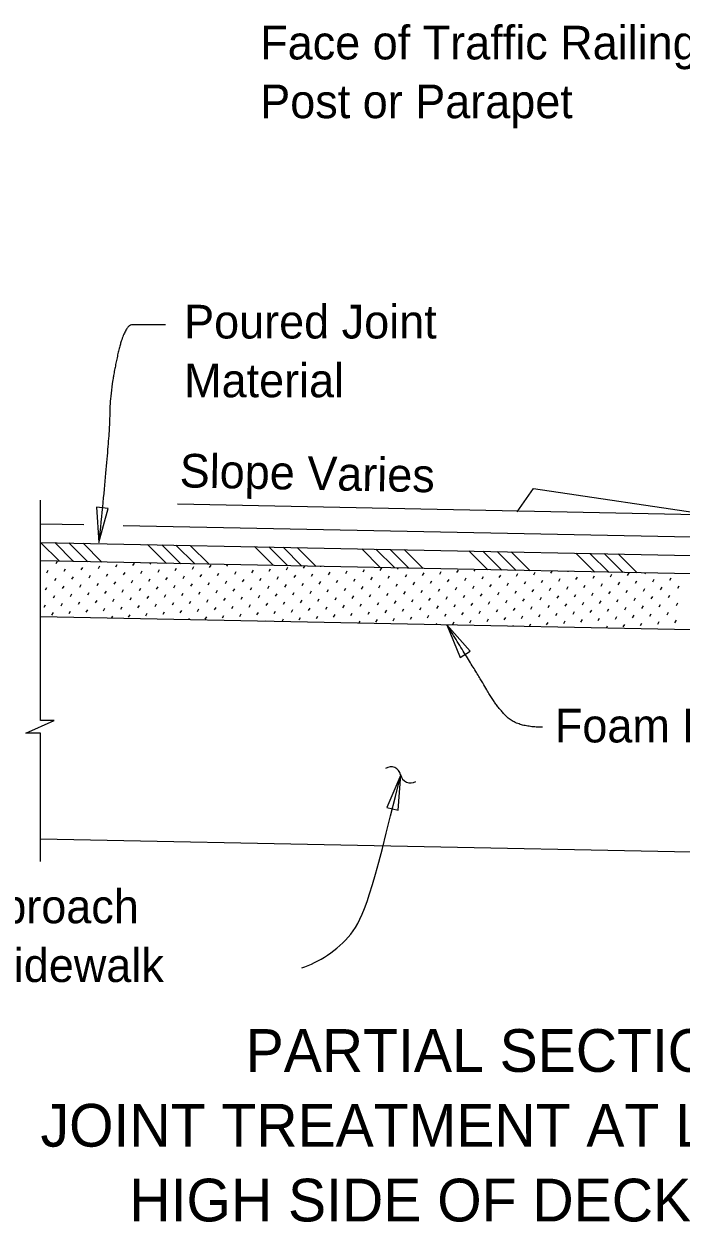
# Model space of a CAD drawing. Extents: x -7.9 to 27, y -3.1 to 14.6.
# Drawn here: x 9.806 to 11.283, y 11.645 to 14.336 of the extents above; entities that cross this region are included whole.
import ezdxf

# ---------------------------------------------------------------- set-up
doc = ezdxf.new("R2010")
doc.units = 0
for name, color, linetype in [('Border', 7, 'Continuous'), ('Patterning', 7, 'Continuous'), ('PlotBorder_dp', 7, 'Continuous'), ('TextMisc', 7, 'Continuous')]:
    doc.layers.add(name, color=color, linetype=linetype)

msp = doc.modelspace()

# ---------------------------------------------------------------- linework, layer by layer
at = {"layer": 'Patterning'}
for p, q in [((9.8432, 13.2133), (9.9407, 13.2114)), ((10.0289, 13.2096), (11.9108, 13.172)), ((13.1635, 12.4386), (9.8432, 12.5051))]:
    msp.add_line(p, q, dxfattribs=at)
at = {"layer": 'PlotBorder_dp'}
for points in [[(10.9147, 13.2405), (10.9512, 13.2929), (11.3547, 13.2329), (10.1512, 13.257)], [(9.8431, 12.4546), (9.8431, 12.7428), (9.8101, 12.7428), (9.8741, 12.7711), (9.8431, 12.7711), (9.8431, 13.2661)]]:
    msp.add_lwpolyline(points, dxfattribs=at)
for points in [[(9.974, 13.1713), (9.9952, 13.2476), (9.9689, 13.2503)], [(10.7562, 12.9866), (10.7863, 12.9133), (10.8087, 12.9273)], [(10.6527, 12.6491), (10.6214, 12.5763), (10.6471, 12.57)]]:
    msp.add_lwpolyline(points, close=True, dxfattribs=at)
for centre, start, end in [((10.6305, 12.645), 10.958, 122.6852), ((10.6744, 12.6535), 190.958, 302.6852)]:
    msp.add_arc(centre, 0.0224, start, end, dxfattribs=at)
for points, degree in [([(10.1242, 13.6601), (10.0676, 13.6601), (10.0307, 13.6601), (9.9987, 13.5086), (9.9987, 13.4101), (9.9741, 13.1713)], 2), ([(10.9716, 12.7564), (10.9138, 12.7564), (10.867, 12.8044), (10.8338, 12.8623), (10.7562, 12.9866)], 2), ([(10.4305, 12.216), (10.4677, 12.2279), (10.5536, 12.281), (10.5865, 12.377), (10.6526, 12.6491)], 3)]:
    msp.add_open_spline(points, degree=degree, dxfattribs=at)
at = {"layer": 'TextMisc'}
for p, q in [((9.8432, 13.1716), (9.8858, 13.1291)), ((9.8432, 13.1716), (11.9731, 13.129)), ((9.875, 13.171), (9.9176, 13.1284)), ((9.9069, 13.1704), (9.9494, 13.1278)), ((9.9387, 13.1697), (9.9813, 13.1272)), ((10.0838, 13.1668), (10.1263, 13.1243)), ((10.1156, 13.1662), (10.1582, 13.1236)), ((10.1475, 13.1655), (10.19, 13.123)), ((10.1793, 13.1649), (10.2219, 13.1223)), ((10.3244, 13.162), (10.3669, 13.1194)), ((10.3562, 13.1614), (10.3988, 13.1188)), ((10.3881, 13.1607), (10.4306, 13.1182)), ((10.4199, 13.1601), (10.4625, 13.1175)), ((10.565, 13.1572), (10.6075, 13.1146)), ((10.5968, 13.1565), (10.6394, 13.114)), ((10.6286, 13.1559), (10.6712, 13.1133)), ((10.6605, 13.1553), (10.703, 13.1127)), ((10.8056, 13.1524), (10.8481, 13.1098)), ((10.8374, 13.1517), (10.88, 13.1092)), ((10.8692, 13.1511), (10.9118, 13.1085)), ((10.9011, 13.1505), (10.9436, 13.1079)), ((11.0462, 13.1475), (11.0887, 13.105)), ((11.078, 13.1469), (11.1206, 13.1044)), ((11.1098, 13.1463), (11.1524, 13.1037)), ((11.1417, 13.1456), (11.1842, 13.1031)), ((11.9723, 13.0873), (9.8432, 13.1299)), ((9.8575, 13.1033), (9.8607, 13.1089)), ((9.8784, 13.1243), (9.8813, 13.1292)), ((9.8962, 13.1066), (9.8994, 13.1122)), ((9.9171, 13.1275), (9.9176, 13.1284)), ((9.9348, 13.1098), (9.9381, 13.1154)), ((9.9735, 13.113), (9.9767, 13.1186)), ((10.0122, 13.1163), (10.0154, 13.1219)), ((10.0508, 13.1195), (10.0541, 13.1251)), ((10.0686, 13.1018), (10.0718, 13.1074)), ((10.0895, 13.1228), (10.0908, 13.125)), ((10.1072, 13.105), (10.1105, 13.1106)), ((10.1459, 13.1083), (10.1491, 13.1139)), ((10.1846, 13.1115), (10.1878, 13.1171)), ((10.2232, 13.1148), (10.2265, 13.1204)), ((10.2619, 13.118), (10.2639, 13.1215)), ((10.2796, 13.1003), (10.2829, 13.1059)), ((10.3183, 13.1035), (10.3215, 13.1091)), ((10.357, 13.1068), (10.3602, 13.1124)), ((10.3956, 13.11), (10.3989, 13.1156)), ((10.4343, 13.1133), (10.4371, 13.118)), ((10.473, 13.1165), (10.4734, 13.1173)), ((10.5294, 13.102), (10.5326, 13.1076)), ((10.568, 13.1053), (10.5713, 13.1109)), ((10.6067, 13.1085), (10.6099, 13.1141)), ((10.6454, 13.1117), (10.6466, 13.1138)), ((10.7404, 13.1005), (10.7437, 13.1061)), ((10.7791, 13.1038), (10.7823, 13.1094)), ((10.8178, 13.107), (10.8197, 13.1104)), ((10.9901, 13.1022), (10.9928, 13.1069)), ((11.0288, 13.1055), (11.0292, 13.1062)), ((9.8752, 13.0856), (9.8784, 13.0912)), ((9.9139, 13.0888), (9.9171, 13.0944)), ((9.9525, 13.0921), (9.9558, 13.0977)), ((9.9703, 13.0744), (9.9735, 13.08)), ((9.9912, 13.0953), (9.9945, 13.1009)), ((10.0089, 13.0776), (10.0122, 13.0832)), ((10.0299, 13.0986), (10.0331, 13.1042)), ((10.0476, 13.0808), (10.0508, 13.0864)), ((10.0863, 13.0841), (10.0895, 13.0897)), ((10.1249, 13.0873), (10.1282, 13.0929)), ((10.1636, 13.0906), (10.1668, 13.0962)), ((10.1813, 13.0729), (10.1846, 13.0785)), ((10.2023, 13.0938), (10.2055, 13.0994)), ((10.22, 13.0761), (10.2232, 13.0817)), ((10.2409, 13.0971), (10.2442, 13.1027)), ((10.2587, 13.0793), (10.2619, 13.0849)), ((10.2973, 13.0826), (10.3006, 13.0882)), ((10.336, 13.0858), (10.3392, 13.0914)), ((10.3747, 13.0891), (10.3779, 13.0947)), ((10.4133, 13.0923), (10.4166, 13.0979)), ((10.4311, 13.0746), (10.4343, 13.0802)), ((10.452, 13.0955), (10.4553, 13.1011)), ((10.4697, 13.0778), (10.473, 13.0834)), ((10.4907, 13.0988), (10.4939, 13.1044)), ((10.5084, 13.0811), (10.5116, 13.0867)), ((10.5471, 13.0843), (10.5503, 13.0899)), ((10.5857, 13.0876), (10.589, 13.0932)), ((10.6244, 13.0908), (10.6276, 13.0964)), ((10.6421, 13.0731), (10.6454, 13.0787)), ((10.6631, 13.094), (10.6663, 13.0996)), ((10.6808, 13.0763), (10.684, 13.0819)), ((10.7017, 13.0973), (10.705, 13.1029)), ((10.7195, 13.0796), (10.7227, 13.0852)), ((10.7581, 13.0828), (10.7614, 13.0884)), ((10.7968, 13.086), (10.8, 13.0916)), ((10.8355, 13.0893), (10.8387, 13.0949)), ((10.8741, 13.0925), (10.8774, 13.0981)), ((10.8919, 13.0748), (10.8951, 13.0804)), ((10.9128, 13.0958), (10.916, 13.1014)), ((10.9305, 13.0781), (10.9338, 13.0836)), ((10.9515, 13.099), (10.9547, 13.1046)), ((10.9692, 13.0813), (10.9724, 13.0869)), ((11.0079, 13.0845), (11.0111, 13.0901)), ((11.0465, 13.0878), (11.0498, 13.0934)), ((11.0852, 13.091), (11.0884, 13.0966)), ((11.1029, 13.0733), (11.1062, 13.0789)), ((11.1239, 13.0943), (11.1271, 13.0999)), ((11.1416, 13.0765), (11.1448, 13.0821)), ((11.1625, 13.0975), (11.1658, 13.1031)), ((11.1803, 13.0798), (11.1835, 13.0854)), ((11.2012, 13.1007), (11.2024, 13.1027)), ((11.2189, 13.083), (11.2222, 13.0886)), ((11.2576, 13.0863), (11.2608, 13.0919)), ((9.8542, 13.0646), (9.8575, 13.0702)), ((9.872, 13.0469), (9.8752, 13.0525)), ((9.8929, 13.0679), (9.8962, 13.0735)), ((9.9106, 13.0502), (9.9139, 13.0558)), ((9.9316, 13.0711), (9.9348, 13.0767)), ((9.9493, 13.0534), (9.9525, 13.059)), ((9.988, 13.0567), (9.9912, 13.0623)), ((10.0266, 13.0599), (10.0299, 13.0655)), ((10.0653, 13.0631), (10.0686, 13.0687)), ((10.104, 13.0664), (10.1072, 13.072)), ((10.1217, 13.0487), (10.1249, 13.0543)), ((10.1427, 13.0696), (10.1459, 13.0752)), ((10.1604, 13.0519), (10.1636, 13.0575)), ((10.199, 13.0551), (10.2023, 13.0607)), ((10.2377, 13.0584), (10.2409, 13.064)), ((10.2764, 13.0616), (10.2796, 13.0672)), ((10.315, 13.0649), (10.3183, 13.0705)), ((10.3328, 13.0472), (10.336, 13.0527)), ((10.3537, 13.0681), (10.357, 13.0737)), ((10.3714, 13.0504), (10.3747, 13.056)), ((10.3924, 13.0713), (10.3956, 13.0769)), ((10.4101, 13.0536), (10.4133, 13.0592)), ((10.4488, 13.0569), (10.452, 13.0625)), ((10.4874, 13.0601), (10.4907, 13.0657)), ((10.5261, 13.0634), (10.5294, 13.069)), ((10.5438, 13.0456), (10.5471, 13.0512)), ((10.5648, 13.0666), (10.568, 13.0722)), ((10.5825, 13.0489), (10.5857, 13.0545)), ((10.6034, 13.0698), (10.6067, 13.0754)), ((10.6212, 13.0521), (10.6244, 13.0577)), ((10.6598, 13.0554), (10.6631, 13.061)), ((10.6985, 13.0586), (10.7017, 13.0642)), ((10.7372, 13.0618), (10.7404, 13.0674)), ((10.7758, 13.0651), (10.7791, 13.0707)), ((10.7936, 13.0474), (10.7968, 13.053)), ((10.8145, 13.0683), (10.8178, 13.0739)), ((10.8322, 13.0506), (10.8355, 13.0562)), ((10.8532, 13.0716), (10.8564, 13.0772)), ((10.8709, 13.0539), (10.8741, 13.0595)), ((10.9096, 13.0571), (10.9128, 13.0627)), ((10.9482, 13.0603), (10.9515, 13.0659)), ((10.9869, 13.0636), (10.9901, 13.0692)), ((11.0046, 13.0459), (11.0079, 13.0515)), ((11.0256, 13.0668), (11.0288, 13.0724)), ((11.0433, 13.0491), (11.0465, 13.0547)), ((11.0642, 13.0701), (11.0675, 13.0757)), ((11.082, 13.0523), (11.0852, 13.0579)), ((11.1206, 13.0556), (11.1239, 13.0612)), ((11.1593, 13.0588), (11.1625, 13.0644)), ((11.198, 13.0621), (11.2012, 13.0677)), ((11.2366, 13.0653), (11.2399, 13.0709)), ((11.2544, 13.0476), (11.2576, 13.0532)), ((11.2753, 13.0685), (11.2786, 13.0741)), ((9.851, 13.026), (9.8542, 13.0316)), ((9.8897, 13.0292), (9.8929, 13.0348)), ((9.9283, 13.0325), (9.9316, 13.0381)), ((9.967, 13.0357), (9.9703, 13.0413)), ((10.0057, 13.0389), (10.0089, 13.0445)), ((10.0234, 13.0212), (10.0266, 13.0268)), ((10.0444, 13.0422), (10.0476, 13.0478)), ((10.0621, 13.0245), (10.0653, 13.0301)), ((10.083, 13.0454), (10.0863, 13.051)), ((10.1007, 13.0277), (10.104, 13.0333)), ((10.1394, 13.0309), (10.1427, 13.0365)), ((10.1781, 13.0342), (10.1813, 13.0398)), ((10.2168, 13.0374), (10.22, 13.043)), ((10.2345, 13.0197), (10.2377, 13.0253)), ((10.2554, 13.0407), (10.2587, 13.0463)), ((10.2731, 13.023), (10.2764, 13.0286)), ((10.2941, 13.0439), (10.2973, 13.0495)), ((10.3118, 13.0262), (10.315, 13.0318)), ((10.3505, 13.0294), (10.3537, 13.035)), ((10.3891, 13.0327), (10.3924, 13.0383)), ((10.4278, 13.0359), (10.4311, 13.0415)), ((10.4665, 13.0392), (10.4697, 13.0448)), ((10.4842, 13.0214), (10.4874, 13.027)), ((10.5052, 13.0424), (10.5084, 13.048)), ((10.5229, 13.0247), (10.5261, 13.0303)), ((10.5615, 13.0279), (10.5648, 13.0335)), ((10.6002, 13.0312), (10.6034, 13.0368)), ((10.6389, 13.0344), (10.6421, 13.04)), ((10.6775, 13.0377), (10.6808, 13.0432)), ((10.6953, 13.0199), (10.6985, 13.0255)), ((10.7162, 13.0409), (10.7195, 13.0465)), ((10.7339, 13.0232), (10.7372, 13.0288)), ((10.7549, 13.0441), (10.7581, 13.0497)), ((10.7726, 13.0264), (10.7758, 13.032)), ((10.8113, 13.0297), (10.8145, 13.0353)), ((10.8499, 13.0329), (10.8532, 13.0385)), ((10.8886, 13.0361), (10.8919, 13.0417)), ((10.9273, 13.0394), (10.9305, 13.045)), ((10.945, 13.0217), (10.9482, 13.0273)), ((10.966, 13.0426), (10.9692, 13.0482)), ((10.9837, 13.0249), (10.9869, 13.0305)), ((11.0223, 13.0281), (11.0256, 13.0337)), ((11.061, 13.0314), (11.0642, 13.037)), ((11.0997, 13.0346), (11.1029, 13.0402)), ((11.1383, 13.0379), (11.1416, 13.0435)), ((11.1561, 13.0202), (11.1593, 13.0258)), ((11.177, 13.0411), (11.1803, 13.0467)), ((11.1947, 13.0234), (11.198, 13.029)), ((11.2157, 13.0444), (11.2189, 13.05)), ((11.2334, 13.0266), (11.2366, 13.0322)), ((11.2721, 13.0299), (11.2753, 13.0355)), ((9.8432, 13.0049), (11.9908, 12.9619)), ((9.8687, 13.0083), (9.872, 13.0139)), ((9.9074, 13.0115), (9.9106, 13.0171)), ((9.9461, 13.0147), (9.9493, 13.0203)), ((9.9669, 13.0024), (9.967, 13.0026)), ((9.9847, 13.018), (9.988, 13.0236)), ((10.0033, 13.0017), (10.0057, 13.0059)), ((10.0411, 13.0035), (10.0444, 13.0091)), ((10.0798, 13.0068), (10.083, 13.0123)), ((10.1185, 13.01), (10.1217, 13.0156)), ((10.1571, 13.0132), (10.1604, 13.0188)), ((10.1764, 12.9982), (10.1781, 13.0011)), ((10.1958, 13.0165), (10.199, 13.0221)), ((10.2135, 12.9988), (10.2168, 13.0044)), ((10.2522, 13.002), (10.2554, 13.0076)), ((10.2908, 13.0052), (10.2941, 13.0108)), ((10.3295, 13.0085), (10.3328, 13.0141)), ((10.3682, 13.0117), (10.3714, 13.0173)), ((10.3859, 12.994), (10.3891, 12.9996)), ((10.4069, 13.015), (10.4101, 13.0206)), ((10.4246, 12.9972), (10.4278, 13.0028)), ((10.4455, 13.0182), (10.4488, 13.0238)), ((10.4632, 13.0005), (10.4665, 13.0061)), ((10.5019, 13.0037), (10.5052, 13.0093)), ((10.5406, 13.007), (10.5438, 13.0126)), ((10.5793, 13.0102), (10.5825, 13.0158)), ((10.597, 12.9925), (10.6002, 12.9981)), ((10.6179, 13.0135), (10.6212, 13.0191)), ((10.6356, 12.9957), (10.6389, 13.0013)), ((10.6566, 13.0167), (10.6598, 13.0223)), ((10.6743, 12.999), (10.6775, 13.0046)), ((10.713, 13.0022), (10.7162, 13.0078)), ((10.7516, 13.0055), (10.7549, 13.0111)), ((10.7903, 13.0087), (10.7936, 13.0143)), ((10.829, 13.0119), (10.8322, 13.0175)), ((10.8467, 12.9942), (10.8499, 12.9998)), ((10.8677, 13.0152), (10.8709, 13.0208)), ((10.8854, 12.9975), (10.8886, 13.0031)), ((10.9063, 13.0184), (10.9096, 13.024)), ((10.924, 13.0007), (10.9273, 13.0063)), ((10.9627, 13.004), (10.966, 13.0095)), ((11.0014, 13.0072), (11.0046, 13.0128)), ((11.0401, 13.0104), (11.0433, 13.016)), ((11.0578, 12.9927), (11.061, 12.9983)), ((11.0787, 13.0137), (11.082, 13.0193)), ((11.0964, 12.996), (11.0997, 13.0016)), ((11.1174, 13.0169), (11.1206, 13.0225)), ((11.1351, 12.9992), (11.1383, 13.0048)), ((11.1738, 13.0024), (11.177, 13.008)), ((11.2124, 13.0057), (11.2157, 13.0113)), ((11.2511, 13.0089), (11.2544, 13.0145)), ((10.3495, 12.9948), (10.3505, 12.9964)), ((10.5227, 12.9913), (10.5229, 12.9916)), ((10.5591, 12.9906), (10.5615, 12.9949)), ((10.7322, 12.9871), (10.7339, 12.9901)), ((10.7694, 12.9877), (10.7726, 12.9933)), ((10.808, 12.991), (10.8113, 12.9966)), ((10.9053, 12.9836), (10.9063, 12.9854)), ((10.9418, 12.983), (10.945, 12.9886)), ((10.9804, 12.9862), (10.9837, 12.9918)), ((11.0191, 12.9895), (11.0223, 12.9951)), ((11.0785, 12.9802), (11.0787, 12.9806)), ((11.1148, 12.9794), (11.1174, 12.9838)), ((11.1528, 12.9815), (11.1561, 12.9871)), ((11.1915, 12.9847), (11.1947, 12.9903)), ((11.2302, 12.988), (11.2334, 12.9936)), ((11.2688, 12.9912), (11.2721, 12.9968))]:
    msp.add_line(p, q, dxfattribs=at)

# ---------------------------------------------------------------- texts
at = {"layer": 'Border'}
msp.add_text('Slope Varies', height=0.0756, rotation=358.8543, dxfattribs=at).set_placement((10.1554, 13.2953))
msp.add_text('Foam Backer Rod', height=0.0756, dxfattribs=at).set_placement((10.9991, 12.7222))
at = {"layer": 'PlotBorder_dp'}
for s, height, p in [('Face of Traffic Railing, ', 0.0756, (10.3369, 14.2563)), ('Post or Parapet', 0.0756, (10.3369, 14.1243)), ('Poured Joint ', 0.0756, (10.1659, 13.6295)), ('Material', 0.0756, (10.1659, 13.4975)), ('Bridge Deck, Approach ', 0.0756, (9.0245, 12.3161)), ('Slab or Raised Sidewalk', 0.0756, (9.0245, 12.1841)), ('PARTIAL SECTION ALONG ℄ JOINT', 0.096, (10.3042, 11.9823)), ('JOINT TREATMENT AT LOW SIDE OF DECK OR', 0.096, (9.8432, 11.8143)), ('HIGH SIDE OF DECK WITH SLOPES < 2%', 0.096, (10.0428, 11.6463))]:
    msp.add_text(s, height=height, dxfattribs=at).set_placement(p)

doc.saveas('drawing.dxf')
